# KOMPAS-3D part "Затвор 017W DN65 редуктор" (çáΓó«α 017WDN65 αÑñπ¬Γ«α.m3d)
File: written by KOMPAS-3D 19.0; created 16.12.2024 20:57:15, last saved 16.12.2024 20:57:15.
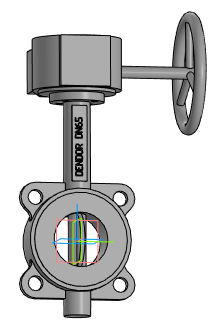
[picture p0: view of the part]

Document properties: Автор: Евгений; Полное имя файла: ..\Затвор 017WDN65 редуктор.a3d

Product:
- Part/product: Затвор 017W DN65 редуктор
    Масса: 11.0019

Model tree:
1. Операция без истории:1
